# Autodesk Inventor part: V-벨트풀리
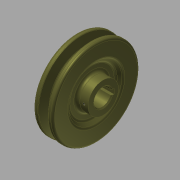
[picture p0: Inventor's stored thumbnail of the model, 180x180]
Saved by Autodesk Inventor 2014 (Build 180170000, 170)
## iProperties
Company: 한국ATC센터
Created: 2015-12
Part Number: V-벨트풀리
Document SubType Name: Modeling
Designer: mdu
Density: 7.25 g/cm^3
Mass: 596.065 g
Surface Area: 214.402 cm^2
Volume: 82.2158 cm^3
Material: 주철
Appearance: 티타늄
Author: mdu
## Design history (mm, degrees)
sketch "스케치1"
  geometry: L1 (-13, 0)-(13, 0); L2 (-13, 0)-(-13, 15); L3 (-13, 15)-(-9, 15); L4 (-9, 15)-(-9, 23); L5 (-9, 23)-(-13, 27); L6 (-13, 27)-(-13, 42.7); L7 (-13, 42.7)-(-8.325, 42.7); L8 (-8.325, 42.7)-(-5.574, 33.7); L9 (-5.574, 33.7)-(-1.426, 33.7); L10 (-1.426, 33.7)-(1.325, 42.7); L11 (1.325, 42.7)-(6, 42.7); L12 (6, 42.7)-(6, 27); L13 (6, 27)-(2, 23); L14 (2, 23)-(2, 15); L15 (2, 15)-(13, 15); L16 (13, 15)-(13, 0); L17 (-7.5, 40)-(0.5, 40); 2 further points
  constraints: 34 end point, 6 parallel, 5 collinear, 5 equal length, 4 perpendicular, 2 point on line, 1 coincident, 1 horizontal, 1 midpoint
  dimensions: "d0" = 26 distance of L1.start L1.end; "d1" = 2.7 distance between parallel lines of L7 L17; "d2" = 6.3 distance between parallel lines of L9 L17; "d3" = 8 distance of L17.start L17.end; "d4" = 34 deg angle of L10 L8; "d5" = 19 distance between parallel lines of L12 L6; "d7" = 30 diameter of L15 L1; "d8" = 46 diameter of L13.end L1; "d9" = 54 diameter of L12.end L1; "d10" = 4 distance between parallel lines of L2 L4; "d11" = 80 diameter of L17 L1
revolve "회전1" sketch "스케치1" stored, may be unused: angle "d12" = 90 deg
sketch "스케치2"
  geometry: L1 (-2.5, 8.124)-(-2.5, 10.8); L2 (-2.5, 10.8)-(2.5, 10.8); L3 (2.5, 10.8)-(2.5, 8.124); A1 r 8.5 centre (0, 0) between (-2.5, 8.124) and (2.5, 8.124); 1 further point
  constraints: 6 end point, 2 parallel, 2 point on circle, 1 centre point, 1 coincident, 1 perpendicular, 1 vertical
  dimensions: "d13" = 17 diameter of A1; "d14" = 19.3 dimension on A1 L2; "d15" = 5 distance of L1.end L2.end
extrude "돌출1" cut sketch "스케치2" stored distance "d16" = 10; taper "d17" = 0 deg
node "작업 평면1"
sketch "스케치3"
  geometry: L1 (-5.5, 15)-(-5.5, -15) reference; L2 (20.5, 27)-(20.5, -27) reference; 3 further points
  constraints: 1 horizontal alignment, 1 midpoint
  dimensions: "d18" = 4 distance from line of point (-1.5, 0) L1; "d33" = 22 distance from line of point (-1.5, 0) L2 (derived)
hole "구멍1" sketch "스케치3" at (-1.5, 0) diameter "d19" = 2.459; stored, may be unused: countersink angle "d23" = 90 deg, drill point angle "d25" = 118 deg; dims "d20" = 6, "d21" = 4, "d22" = 2, "d24" = 8
fillet "모깎기1" dims "d26" = 2, "d27" = 0.5, "d28" = 1, "d29" = 3
chamfer "모따기1" distance "d30" = 1; stored, may be unused: second distance "d31" = 2, angle "d32" = 45 deg
sketch "스케치4" dims "d35" = 70
  geometry: C1 r 2 at (35, 0); 2 further points
  constraints: 2 horizontal alignment, 1 centre point, 1 coincident, 2 other
  dimensions: "d34" = 4 diameter of C1
extrude "돌출2" cut sketch "스케치4" distance "d36" = 1; taper "d37" = 0 deg
fillet "모깎기3" dims "d40" = 0.5
node "솔리드1"
